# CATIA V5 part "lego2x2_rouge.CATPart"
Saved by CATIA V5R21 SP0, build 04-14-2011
Part number: lego2x2_rouge
Definition: Brique LEGO® 2x2, couleur Rouge
Description: Brique LEGO® 2x2, couleur Rouge
Property "SUPPLIER": "LEGO®"
Property "SUPPLIER": "LEGO®"
Property "DESIGN": "Brique LEGO® 2x2, couleur Rouge"
Property "DESIGN": "Brique LEGO® 2x2, couleur Rouge"
Property "TraceParts.PartNumber": "10-20122010-068626"
Property "TraceParts.PartTitle": "Brique LEGO® 2x2, couleur Rouge"
Property "TraceParts.InstanceId": "10-20122010-06862610UFQ9W313DGN2O2A8ITDW7CR"
Property "TraceParts.PartVersion": "1.0.7"
Property "TraceParts.PartLanguage": "fr"
Bounding box of the stored display mesh (mm): x -4 to 12, y 0 to 11.2, z -4 to 12
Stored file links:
  C:\Users\2027.DESARCY-LEMIE30\Desktop\lego2x2_rouge.CATPart
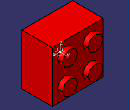
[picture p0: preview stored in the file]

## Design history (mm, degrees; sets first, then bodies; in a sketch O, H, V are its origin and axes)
AxisSystem1: origin (0, 0, 0), X (1, 0, 0), Y (0, 1, 0), Z (0, 0, 1)
Body1 "lego2x2_rouge" (main body)
  Solid1: solid without history
  Sketch1 on face of Solid1, origin (0, 0, 0), H (1, 0, 0), V (0, 0, 1)
    line L1 (-3, 11) -> (11, 11)
    line L2 (11, 11) -> (11, -3)
    line L3 (11, -3) -> (-3, -3)
    line L4 (-3, -3) -> (-3, 11)
    reference projected line E1 (12, -4) -> (12, 12) from edge [face of Solid1 | face of Solid1]
    reference projected line E2 (-4, 12) -> (12, 12) from edge [face of Solid1 | face of Solid1]
    reference projected line E3 (-4, -4) -> (-4, 12) from edge [face of Solid1 | face of Solid1]
    reference projected line E4 (-4, -4) -> (12, -4) from edge [face of Solid1 | face of Solid1]
    circle A1 centre (4, 4) radius 3
    point P5 (4, 4)
    reference projected circle E5 centre (4, 4) radius 2.4 from edge [face of Solid1 | face of Solid1]
    distance L2 E1 = 1
    distance L1 E2 = 1
    distance L4 E3 = 1
    distance E4 L3 = 1
    radius A1 = 3
    horizontal: L1 H, L3 H
    vertical: L2 V, L4 V
    concentricity: P5 E5
  Pocket1: profile Sketch1, direction (0, 1, 0), length 9
  Sketch2 on face of Solid1, origin (0, 1.6, 0), H (1, 0, 0), V (0, 0, 1)
    circle A1 centre (4, 4) radius 2.4
    point P1 (4, 4)
    reference projected circle E1 centre (4, 4) radius 2.4 from edge [face of Solid1 | face of Solid1]
    reference projected circle E2 centre (4, 4) radius 2.4 from edge [face of Solid1 | face of Solid1]
    concentricity: P1 E1
    coincidence: A1 E2
  Pocket2: profile Sketch2, direction (0, 1, 0), length 7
